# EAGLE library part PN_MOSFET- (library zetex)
DUAL N AND P-CHANNEL ENHANCEMENT MODE MOSFET source ZXMD63C02.pdf from http://www.zetex.com/
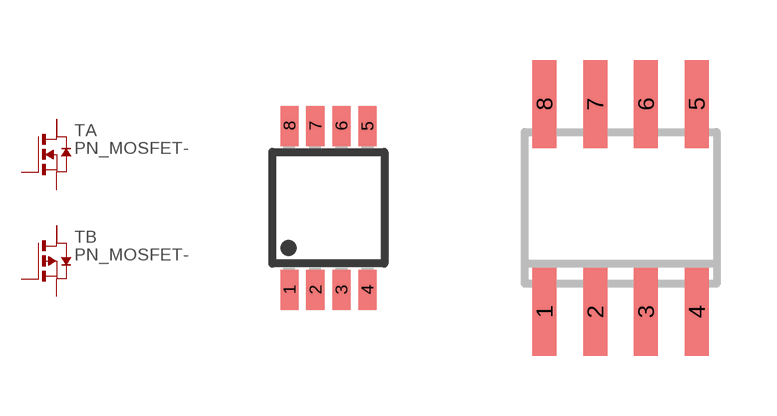
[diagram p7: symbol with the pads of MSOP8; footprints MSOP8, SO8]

Designator prefix T; gates B=P_MOS2D A=N_MOS2D

## PN_MOSFET-MSOP8 (OC_FARNELL: unknown; OC_NEWARK: unknown)  [MSOP8]
1  A:S  pas
2  A:G  pas
3  B:S  pas
4  B:G  pas
5  B:D  pas
6  B:D2  pas
7  A:D  pas
8  A:D2  pas

## PN_MOSFET-SO8 (OC_FARNELL: unknown; OC_NEWARK: unknown)  [SO8]
Pads as for MSOP8

## Footprint MSOP8 (pad centres in mm)
Micro Small Outline Package
smd 0.45 x 1: 1 -0.975,-2.05; 2 -0.325,-2.05; 3 0.325,-2.05; 4 0.975,-2.05; 5 0.975,2.05; 6 0.325,2.05; 7 -0.325,2.05; 8 -0.975,2.05

## Footprint SO8 (pad centres in mm)
SMALL OUTLINE INTEGRATED CIRCUIT
smd 0.6 x 2.2: 1 -1.905,-2.6; 2 -0.635,-2.6; 3 0.635,-2.6; 4 1.905,-2.6; 5 1.905,2.6; 6 0.635,2.6; 7 -0.635,2.6; 8 -1.905,2.6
